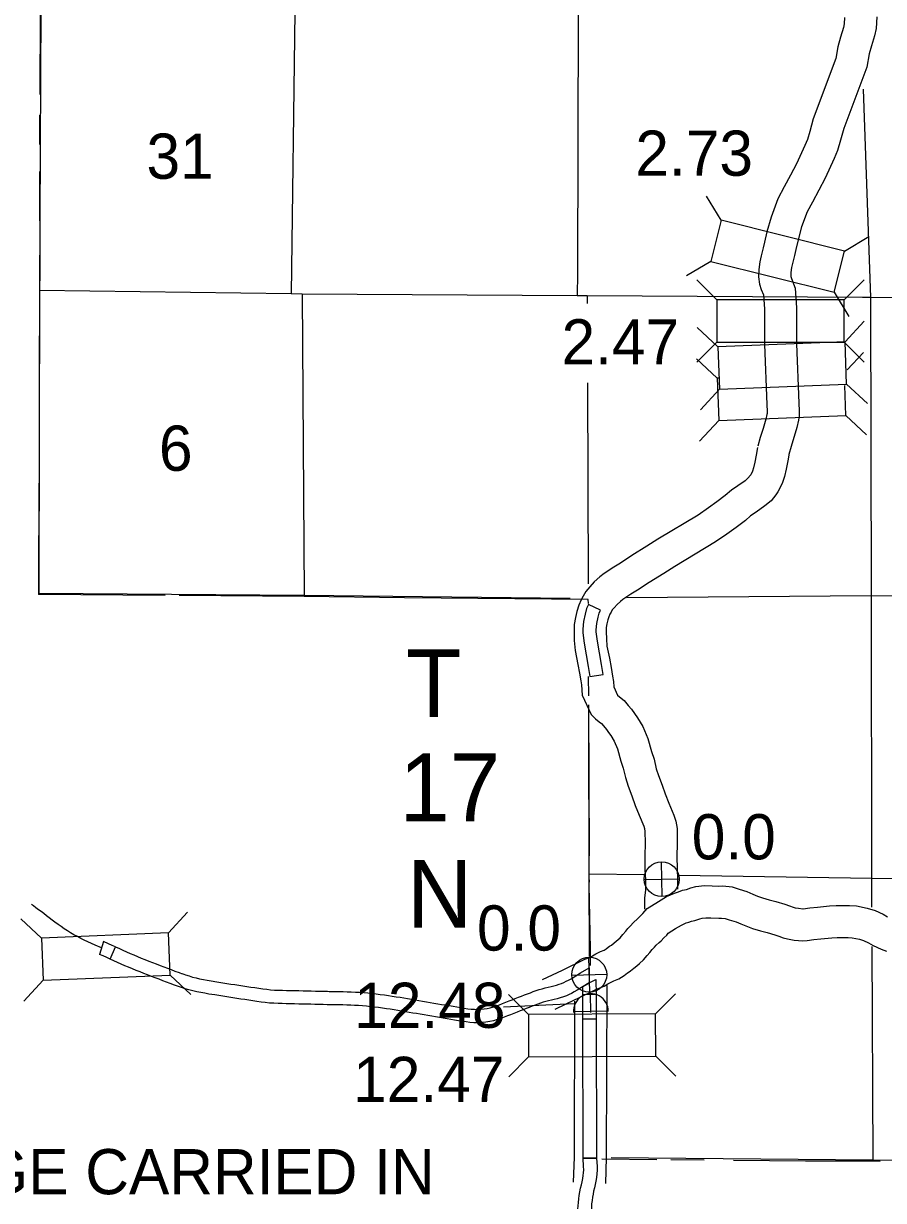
# Model space of a CAD drawing. Extents: x 77230 to 630905, y 790554 to 1662844.
# Drawn here: x 417367 to 433436, y 1503964 to 1525962 of the extents above; entities that cross this region are included whole.
import ezdxf

# ---------------------------------------------------------------- set-up
doc = ezdxf.new("R2010")
doc.units = 0
for name, color, linetype in [('Level 10', 7, 'Continuous'), ('Level 15', 7, 'Continuous'), ('Level 16', 7, 'Continuous'), ('Level 18', 7, 'Continuous'), ('Level 19', 7, 'Continuous'), ('Level 22', 7, 'Continuous'), ('Level 23', 7, 'Continuous'), ('Level 28', 7, 'Continuous'), ('Level 31', 7, 'Continuous'), ('Level 32', 7, 'Continuous'), ('Level 34', 7, 'Continuous'), ('Level 43', 7, 'Continuous')]:
    doc.layers.add(name, color=color, linetype=linetype)

msp = doc.modelspace()

# ---------------------------------------------------------------- linework, layer by layer
at = {"layer": 'Level 10'}
for p, q in [((427815, 1507814), (427821, 1507962)), ((428062, 1508096), (428065, 1507807)), ((427815, 1507362), (427815, 1507814)), ((428065, 1507807), (427815, 1507814)), ((428065, 1507807), (428065, 1507362)), ((427815, 1507362), (428065, 1507362)), ((428072, 1504757), (427822, 1504756))]:
    msp.add_line(p, q, dxfattribs=at)
for points in [[(428149, 1514996), (427923, 1515103), (427889, 1515031), (427859, 1514925), (427831, 1514784), (427819, 1514641), (427820, 1514574), (427843, 1514383), (427920, 1513944), (427949, 1513759), (428196, 1513798)], [(428196, 1513798), (428166, 1513985), (428090, 1514419), (428070, 1514591), (428069, 1514633), (428079, 1514749), (428102, 1514866), (428124, 1514943), (428149, 1514996)], [(427821, 1507962), (427938, 1508033), (428062, 1508096)], [(427822, 1504756), (427815, 1507362)], [(428065, 1507362), (428072, 1504757)], [(427712, 1503430), (427717, 1503485), (427714, 1503526), (427708, 1503599), (427723, 1503681), (427724, 1503736), (427727, 1503800), (427730, 1503861), (427734, 1503927), (427743, 1503997), (427751, 1504060), (427763, 1504127), (427776, 1504192), (427790, 1504255), (427804, 1504314), (427815, 1504372), (427825, 1504430), (427832, 1504483), (427834, 1504537), (427833, 1504598), (427822, 1504756), (428072, 1504757)], [(428072, 1504757), (428083, 1504600), (428084, 1504533), (428081, 1504461), (428072, 1504393), (428061, 1504328), (428048, 1504262), (428034, 1504199), (428020, 1504139), (428008, 1504081), (427998, 1504023), (427991, 1503966), (427983, 1503904), (427980, 1503849), (427977, 1503788), (427974, 1503726), (427972, 1503656), (427960, 1503588), (427964, 1503546), (427968, 1503483), (427961, 1503408)], [(428072, 1504757), (428083, 1504600), (428084, 1504533), (428081, 1504461), (428072, 1504393), (428061, 1504328), (428048, 1504262), (428034, 1504199), (428020, 1504139), (428008, 1504081), (427998, 1504023), (427991, 1503966), (427983, 1503904), (427980, 1503849), (427977, 1503788), (427974, 1503726), (427972, 1503656), (427960, 1503588), (427964, 1503546), (427968, 1503483), (427961, 1503408)]]:
    msp.add_lwpolyline(points, dxfattribs=at)
at = {"layer": 'Level 15'}
for p, q in [((420331, 1508203), (420328, 1508204)), ((420246, 1507968), (420244, 1507969)), ((427172, 1507952), (427173, 1507952)), ((427231, 1507709), (427232, 1507709))]:
    msp.add_line(p, q, dxfattribs=at)
for points in [[(442784, 1520763), (438511, 1520777), (438354, 1520782), (433196, 1520844), (433042, 1520842), (427898, 1520874), (427715, 1520873), (422575, 1520905), (422367, 1520911), (417667, 1520973)], [(418823, 1508684), (418702, 1508738), (418634, 1508769), (418568, 1508799), (418502, 1508831), (418436, 1508863), (418372, 1508896), (418309, 1508931), (418247, 1508967), (418186, 1509005), (418127, 1509043), (418068, 1509082), (418011, 1509123), (417954, 1509164), (417900, 1509206), (417847, 1509247), (417795, 1509287), (417744, 1509326), (417694, 1509363), (417645, 1509399), (417597, 1509434), (417550, 1509469), (417517, 1509494)], [(419086, 1508704), (419023, 1508731), (418956, 1508761), (418859, 1508805), (418787, 1508563)], [(420244, 1507969), (420187, 1507990), (420108, 1508019), (420039, 1508045), (419970, 1508072), (419900, 1508098), (419829, 1508125), (419757, 1508152), (419686, 1508180), (419615, 1508207), (419543, 1508235), (419471, 1508264), (419401, 1508294), (419330, 1508323), (419261, 1508353), (419192, 1508383), (419124, 1508413), (419056, 1508443), (418986, 1508475), (419086, 1508704)], [(419086, 1508704), (419157, 1508672), (419224, 1508642), (419292, 1508612), (419360, 1508583), (419428, 1508553), (419497, 1508524), (419566, 1508495), (419635, 1508467), (419705, 1508440), (419776, 1508413), (419847, 1508385), (419918, 1508358), (419988, 1508332), (420058, 1508305), (420128, 1508279), (420196, 1508253), (420274, 1508224), (420331, 1508203)], [(418986, 1508475), (418920, 1508503), (418853, 1508534), (418787, 1508563)], [(420328, 1508204), (420394, 1508181), (420459, 1508161), (420526, 1508141), (420591, 1508123), (420656, 1508109), (420727, 1508096), (420798, 1508082), (420870, 1508070), (420981, 1508053), (421017, 1508047), (421093, 1508035), (421167, 1508022), (421242, 1508010), (421316, 1507999), (421391, 1507987), (421466, 1507976), (421541, 1507965), (421616, 1507954), (421691, 1507942), (421766, 1507931), (421839, 1507920), (421912, 1507911), (421984, 1507904), (422057, 1507898), (422132, 1507895), (422207, 1507892), (422283, 1507890), (422360, 1507889), (422437, 1507887), (422514, 1507886), (422591, 1507885), (422667, 1507883), (422744, 1507882), (422820, 1507879), (422895, 1507877), (422970, 1507875), (423044, 1507874), (423075, 1507873), (423192, 1507871), (423266, 1507869), (423340, 1507868), (423415, 1507866), (423491, 1507864), (423568, 1507860), (423645, 1507856), (423724, 1507850), (423802, 1507843), (423880, 1507835), (423957, 1507826), (424033, 1507817), (424109, 1507807), (424184, 1507796), (424258, 1507785), (424331, 1507773), (424403, 1507762), (424474, 1507750), (424544, 1507738), (424614, 1507726), (424683, 1507714), (424753, 1507702), (424824, 1507690), (424895, 1507678), (424965, 1507666), (425036, 1507654), (425108, 1507642), (425180, 1507630), (425251, 1507618), (425323, 1507606), (425394, 1507594), (425464, 1507582), (425534, 1507570), (425602, 1507559), (425668, 1507549), (425732, 1507541), (425793, 1507537), (425854, 1507536), (425915, 1507539), (425974, 1507545), (426031, 1507554), (426089, 1507567), (426146, 1507583), (426202, 1507602), (426260, 1507624), (426319, 1507647), (426379, 1507670), (426440, 1507693), (426497, 1507715), (426554, 1507738), (426613, 1507762), (426670, 1507783), (426726, 1507805), (426782, 1507826), (426837, 1507847), (426892, 1507868), (426948, 1507888), (427005, 1507907), (427061, 1507923), (427117, 1507938), (427172, 1507952)], [(427173, 1507952), (427226, 1507965), (427278, 1507978), (427328, 1507991), (427374, 1508005), (427419, 1508022), (427464, 1508040), (427508, 1508061), (427553, 1508083), (427598, 1508107), (427774, 1508216), (427937, 1508314), (427938, 1508033)], [(427232, 1507709), (427179, 1507696), (427128, 1507683), (427078, 1507668), (427029, 1507652), (426979, 1507634), (426926, 1507614), (426871, 1507593), (426816, 1507572), (426760, 1507550), (426703, 1507528), (426648, 1507507), (426589, 1507482), (426528, 1507460), (426469, 1507437), (426410, 1507414), (426349, 1507390), (426286, 1507367), (426219, 1507344), (426150, 1507325), (426080, 1507309), (426007, 1507297), (425933, 1507289), (425858, 1507286), (425783, 1507287), (425708, 1507292), (425635, 1507301), (425563, 1507312), (425493, 1507324), (425422, 1507336), (425352, 1507348), (425281, 1507359), (425210, 1507372), (425138, 1507384), (425067, 1507396), (424995, 1507407), (424924, 1507419), (424852, 1507432), (424781, 1507444), (424711, 1507456), (424641, 1507468), (424571, 1507480), (424502, 1507492), (424432, 1507503), (424362, 1507515), (424291, 1507527), (424219, 1507538), (424147, 1507549), (424075, 1507560), (424002, 1507569), (423928, 1507578), (423853, 1507586), (423778, 1507594), (423703, 1507601), (423629, 1507606), (423554, 1507611), (423481, 1507614), (423408, 1507616), (423335, 1507618), (423261, 1507619), (423187, 1507621), (423070, 1507623), (423039, 1507624), (422964, 1507625), (422888, 1507627), (422813, 1507630), (422738, 1507632), (422662, 1507633), (422586, 1507635), (422509, 1507636), (422432, 1507637), (422355, 1507639), (422277, 1507641), (422200, 1507643), (422122, 1507645), (422043, 1507649), (421963, 1507655), (421884, 1507662), (421806, 1507673), (421729, 1507684), (421654, 1507695), (421579, 1507706), (421504, 1507718), (421429, 1507729), (421354, 1507740), (421278, 1507752), (421203, 1507763), (421127, 1507776), (421052, 1507788), (420978, 1507800), (420943, 1507806), (420829, 1507823), (420754, 1507836), (420681, 1507850), (420607, 1507864), (420530, 1507880), (420458, 1507901), (420387, 1507921), (420316, 1507944), (420246, 1507968)], [(427938, 1508033), (427713, 1507892), (427657, 1507861), (427604, 1507832), (427565, 1507811), (427510, 1507789), (427454, 1507768), (427397, 1507750), (427341, 1507735), (427285, 1507722), (427231, 1507709)]]:
    msp.add_lwpolyline(points, dxfattribs=at)
at = {"layer": 'Level 16'}
for points in [[(422260, 1549746), (422258, 1547455), (422316, 1542130), (422366, 1536889), (422412, 1531588), (422437, 1526179), (422367, 1520911)], [(427633, 1540013), (427661, 1536861), (427691, 1531632), (427728, 1526176), (427716, 1521298)], [(433059, 1524734), (433196, 1520844)], [(427716, 1521298), (427715, 1520873)], [(422575, 1520905), (422612, 1515279)], [(427898, 1520882), (427899, 1520731)], [(433196, 1520844), (433204, 1515270), (433211, 1509975), (433213, 1509445)], [(427904, 1519246), (427917, 1515489)], [(442828, 1515198), (438508, 1515205), (433198, 1515264), (428642, 1515227)], [(428969, 1510048), (427933, 1510064)], [(435103, 1509968), (433219, 1509983), (429610, 1510038)], [(433217, 1508712), (433236, 1504726)]]:
    msp.add_lwpolyline(points, dxfattribs=at)
at = {"layer": 'Level 18'}
for points in [[(407401, 1549518), (407365, 1547542), (407301, 1542250), (407239, 1536976), (407211, 1531759), (409819, 1531746), (409752, 1526450), (412435, 1526374), (417689, 1526263), (417667, 1520973), (417653, 1515469), (417654, 1515315), (422612, 1515279), (427579, 1515225)], [(427925, 1512841), (427933, 1510064), (427939, 1508522)], [(428346, 1504767), (433236, 1504726), (438492, 1504667), (443044, 1504611)]]:
    msp.add_lwpolyline(points, dxfattribs=at)
at = {"layer": 'Level 19'}
for p, q in [((430403, 1522285), (430131, 1522738)), ((432708, 1521709), (433161, 1521981)), ((430211, 1521517), (429758, 1521245)), ((430324, 1520798), (429950, 1521171)), ((432700, 1520799), (433073, 1521172)), ((432516, 1520941), (432788, 1520488)), ((430343, 1519920), (429956, 1520279)), ((432718, 1520010), (433077, 1520397)), ((430324, 1520006), (429951, 1519632)), ((432718, 1520010), (430343, 1519920)), ((430343, 1519920), (430373, 1519129)), ((432700, 1520007), (433073, 1519634)), ((432747, 1519219), (432718, 1520010)), ((430329, 1519336), (429941, 1519695)), ((432760, 1519487), (433062, 1519813)), ((430352, 1519337), (430329, 1519336)), ((430329, 1519336), (430358, 1518544)), ((430373, 1519129), (432747, 1519219)), ((432733, 1518634), (432712, 1519197)), ((432747, 1519219), (433135, 1518859)), ((430373, 1519129), (430014, 1518742)), ((430358, 1518544), (429999, 1518157)), ((430358, 1518544), (432733, 1518634)), ((432733, 1518634), (433120, 1518275)), ((420075, 1508964), (420433, 1509352)), ((417701, 1508870), (417313, 1509229)), ((420106, 1508173), (420494, 1507815)), ((417732, 1508079), (417374, 1507691)), ((426801, 1507441), (426426, 1507812)), ((429177, 1507451), (429549, 1507826)), ((426805, 1506649), (426433, 1506274)), ((429181, 1506659), (429556, 1506287))]:
    msp.add_line(p, q, dxfattribs=at)
for points in [[(432708, 1521709), (430403, 1522285), (430211, 1521517), (432516, 1520941)], [(430324, 1520006), (432700, 1520007), (432700, 1520799), (430324, 1520798)], [(417732, 1508079), (420106, 1508173), (420075, 1508964), (417701, 1508870)], [(426805, 1506649), (429181, 1506659), (429177, 1507451), (426801, 1507441)]]:
    msp.add_lwpolyline(points, close=True, dxfattribs=at)
at = {"layer": 'Level 22'}
for points in [[(432708, 1526074), (432702, 1525954), (432686, 1525886), (432634, 1525707), (432586, 1525530), (432543, 1525310), (432124, 1524184), (432057, 1523944), (432014, 1523795), (431964, 1523681), (431808, 1523337), (431699, 1523129), (431580, 1522911), (431460, 1522686), (431335, 1522345), (431258, 1522066), (431215, 1521876), (431189, 1521767), (431152, 1521619), (431127, 1521511), (431107, 1521365), (431099, 1521228), (431118, 1521091), (431153, 1520991), (431191, 1520889), (431210, 1520626), (431212, 1520431), (431212, 1519964), (431254, 1518841), (431261, 1518713), (431260, 1518672), (431258, 1518653), (431238, 1518566), (431211, 1518480), (431186, 1518395), (431134, 1518222), (431091, 1518062)], [(433309, 1526089), (433298, 1525872), (433267, 1525735), (433211, 1525545), (433170, 1525393), (433122, 1525147), (432695, 1523999), (432634, 1523781), (432580, 1523592), (432512, 1523437), (432347, 1523073), (432228, 1522846), (432108, 1522626), (432008, 1522440), (431907, 1522162), (431840, 1521920), (431799, 1521740), (431772, 1521624), (431735, 1521479), (431718, 1521402), (431704, 1521308), (431702, 1521253), (431704, 1521233), (431718, 1521194), (431783, 1521016), (431810, 1520651), (431812, 1520434), (431812, 1519975), (431854, 1518868), (431861, 1518723), (431859, 1518632), (431850, 1518551), (431817, 1518409), (431785, 1518306), (431761, 1518223), (431711, 1518058), (431670, 1517905)], [(431085, 1518035), (431060, 1517896), (431034, 1517761), (431009, 1517657), (430989, 1517594), (430955, 1517528), (430952, 1517524), (430903, 1517462), (430851, 1517418), (430716, 1517321), (430594, 1517240), (430478, 1517143), (430324, 1517022), (430167, 1516910), (429974, 1516776), (429222, 1516322), (429017, 1516192), (428735, 1516020), (428520, 1515879), (428395, 1515802), (428215, 1515685), (428134, 1515620), (428032, 1515528), (427948, 1515435), (427875, 1515347), (427823, 1515257), (427787, 1515190), (427741, 1515092), (427705, 1514975), (427679, 1514860), (427657, 1514729), (427653, 1514587), (427659, 1514428), (427672, 1514245), (427726, 1513980), (427758, 1513822), (427781, 1513674), (427791, 1513600), (427804, 1513410), (427975, 1513045), (428057, 1512968), (428123, 1512912), (428165, 1512880), (428202, 1512833), (428258, 1512768), (428299, 1512713), (428340, 1512655), (428404, 1512551), (428466, 1512404), (428529, 1512178), (428573, 1512047), (428613, 1511869), (428668, 1511711), (428732, 1511525), (428796, 1511349), (428870, 1511165), (428955, 1510963), (428969, 1510914), (428979, 1510858), (428980, 1510646), (428974, 1510397), (428978, 1510147), (428986, 1509958), (428986, 1509766), (428971, 1509619), (428970, 1509499), (428973, 1509419), (428973, 1509410)], [(431676, 1517932), (431650, 1517786), (431620, 1517633), (431587, 1517495), (431545, 1517366), (431465, 1517207), (431424, 1517154), (431336, 1517043), (431221, 1516945), (431058, 1516827), (430953, 1516758), (430855, 1516676), (430684, 1516542), (430512, 1516419), (430300, 1516272), (429538, 1515812), (429334, 1515682), (429056, 1515513), (428842, 1515373), (428717, 1515296), (428567, 1515198), (428522, 1515162), (428457, 1515103), (428402, 1515043), (428369, 1515003), (428346, 1514963), (428324, 1514921), (428302, 1514875), (428285, 1514819), (428268, 1514745), (428256, 1514672), (428254, 1514590), (428258, 1514460), (428268, 1514327), (428314, 1514100), (428349, 1513926), (428374, 1513762), (428389, 1513664), (428395, 1513562), (428468, 1513407), (428501, 1513379), (428592, 1513308), (428665, 1513215), (428725, 1513145), (428785, 1513065), (428842, 1512984), (428940, 1512825), (429033, 1512601), (429102, 1512356), (429152, 1512210), (429191, 1512033), (429235, 1511908), (429298, 1511726), (429357, 1511563), (429426, 1511392), (429521, 1511163), (429553, 1511055), (429579, 1510916), (429580, 1510639), (429574, 1510395), (429578, 1510165), (429586, 1509970), (429586, 1509781)], [(427065, 1508096), (427436, 1508271), (427857, 1508475)], [(428265, 1507980), (428255, 1504765), (428239, 1504284)], [(427300, 1507543), (427676, 1507720), (427721, 1507739), (428074, 1507916)], [(427664, 1507689), (427655, 1504776), (427639, 1504304)]]:
    msp.add_lwpolyline(points, dxfattribs=at)
at = {"layer": 'Level 23'}
for points in [[(427857, 1508475), (427960, 1508515), (427997, 1508535), (428064, 1508573), (428148, 1508615), (428219, 1508645), (428253, 1508666), (428293, 1508697), (428319, 1508715), (428352, 1508739), (428401, 1508777), (428442, 1508810), (428479, 1508842), (428516, 1508874), (428564, 1508936), (428620, 1508995), (428661, 1509045), (428706, 1509095), (428756, 1509153), (428846, 1509237), (428873, 1509259), (428904, 1509291), (428942, 1509330), (429019, 1509420), (429234, 1509555), (429383, 1509646), (429530, 1509709), (429603, 1509736), (429680, 1509762), (429753, 1509779), (429839, 1509805), (429932, 1509830), (430091, 1509851), (430234, 1509845), (430356, 1509841), (430432, 1509844), (430611, 1509825), (430737, 1509781), (430880, 1509738), (430997, 1509690), (431085, 1509653), (431176, 1509620), (431298, 1509585), (431422, 1509552), (431592, 1509502), (431678, 1509472), (431747, 1509447), (431784, 1509436), (431847, 1509425), (431927, 1509417), (431937, 1509418), (432063, 1509436), (432206, 1509449), (432427, 1509472), (432553, 1509478), (432664, 1509479), (432802, 1509478), (432930, 1509469), (433131, 1509430), (433282, 1509383), (433428, 1509313), (433511, 1509268)], [(428074, 1507916), (428214, 1507970), (428288, 1508011), (428345, 1508042), (428400, 1508070), (428492, 1508109), (428593, 1508170), (428652, 1508216), (428666, 1508226), (428708, 1508255), (428774, 1508306), (428828, 1508350), (428875, 1508391), (428953, 1508460), (429019, 1508543), (429070, 1508597), (429116, 1508653), (429158, 1508699), (429191, 1508738), (429243, 1508787), (429280, 1508818), (429332, 1508871), (429385, 1508925), (429415, 1508960), (429550, 1509045), (429659, 1509112), (429751, 1509151), (429801, 1509169), (429847, 1509185), (429910, 1509200), (430003, 1509228), (430049, 1509241), (430118, 1509250), (430211, 1509246), (430357, 1509240), (430412, 1509243), (430478, 1509236), (430552, 1509210), (430681, 1509171), (430768, 1509136), (430865, 1509095), (430990, 1509049), (431137, 1509007), (431261, 1508974), (431408, 1508931), (431478, 1508906), (431561, 1508876), (431644, 1508852), (431765, 1508830), (431930, 1508815), (432007, 1508823), (432132, 1508840), (432265, 1508852), (432471, 1508874), (432569, 1508878), (432665, 1508879), (432779, 1508878), (432851, 1508873), (432986, 1508847), (433063, 1508823), (433154, 1508779), (433243, 1508730), (433390, 1508664), (433491, 1508627)]]:
    msp.add_lwpolyline(points, dxfattribs=at)
at = {"layer": 'Level 28'}
msp.add_line((424838, 1511685), (424838, 1511685), dxfattribs=at)
at = {"layer": 'Level 31'}
msp.add_line((426335, 1507584), (427659, 1507644), dxfattribs=at)
at = {"layer": 'Level 32'}
msp.add_line((430352, 1519337), (430329, 1519336), dxfattribs=at)
at = {"layer": 'Level 34'}
for p, q in [((429300, 1509644), (429285, 1510295)), ((428967, 1509962), (429618, 1509977)), ((427946, 1507859), (427931, 1508510)), ((427613, 1508177), (428264, 1508192)), ((427969, 1507479), (427961, 1507827)), ((427643, 1507494), (428294, 1507509))]:
    msp.add_line(p, q, dxfattribs=at)
for centre in [(429292, 1509970), (427938, 1508184)]:
    msp.add_circle(centre, 326, dxfattribs=at)
msp.add_arc((427968, 1507502), 326, 359.4455, 184.0126, dxfattribs=at)
at = {"layer": 'Level 43'}
for points in [[(409779, 1527532), (409762, 1526430), (412433, 1526346), (412918, 1526325), (415195, 1526271), (416735, 1526233), (417678, 1526221), (417678, 1526157), (417668, 1524635)], [(417665, 1524249), (417663, 1523956), (417664, 1523699)], [(417666, 1523198), (417671, 1521339), (417663, 1520952)], [(417663, 1520952), (417659, 1519312)], [(417659, 1519101), (417656, 1518186)], [(417654, 1517370), (417649, 1515426), (417648, 1515291)], [(420014, 1515274), (417648, 1515291)], [(427921, 1515122), (427920, 1515200), (424485, 1515230), (422612, 1515255), (420276, 1515272)], [(427928, 1513396), (427927, 1513758)], [(427941, 1510407), (427929, 1513228)], [(427964, 1508355), (427963, 1508667), (427938, 1509860), (427941, 1509958)], [(429202, 1504725), (428171, 1504734)], [(430085, 1504717), (429465, 1504723)], [(433375, 1504694), (433239, 1504696), (432605, 1504700), (431978, 1504698), (430636, 1504711)]]:
    msp.add_lwpolyline(points, dxfattribs=at)

# ---------------------------------------------------------------- texts
at = {"layer": 'Level 16'}
for s, height, p in [('31', 844.8, (419664, 1523061)), ('6', 845, (419897, 1517603))]:
    msp.add_text(s, height=height, dxfattribs=at).set_placement(p)
at = {"layer": 'Level 28'}
for s, height, p in [('T', 1267, (424515, 1512998)), ('17', 1267.2, (424389, 1511052)), ('N', 1267, (424531, 1509063)), ('MILEAGE CARRIED IN', 844.8, (413185, 1504080))]:
    msp.add_text(s, height=height, dxfattribs=at).set_placement(p)
at = {"layer": 'Level 31'}
for s, p in [('0.0', (429853, 1510340)), ('0.0', (425840, 1508635)), ('12.48', (423546, 1507190))]:
    msp.add_text(s, height=844.8, dxfattribs=at).set_placement(p)
at = {"layer": 'Level 32'}
for s, p in [('2.73', (428799, 1523117)), ('2.47', (427420, 1519590)), ('12.47', (423526, 1505805))]:
    msp.add_text(s, height=844.8, dxfattribs=at).set_placement(p)

doc.saveas('drawing.dxf')
